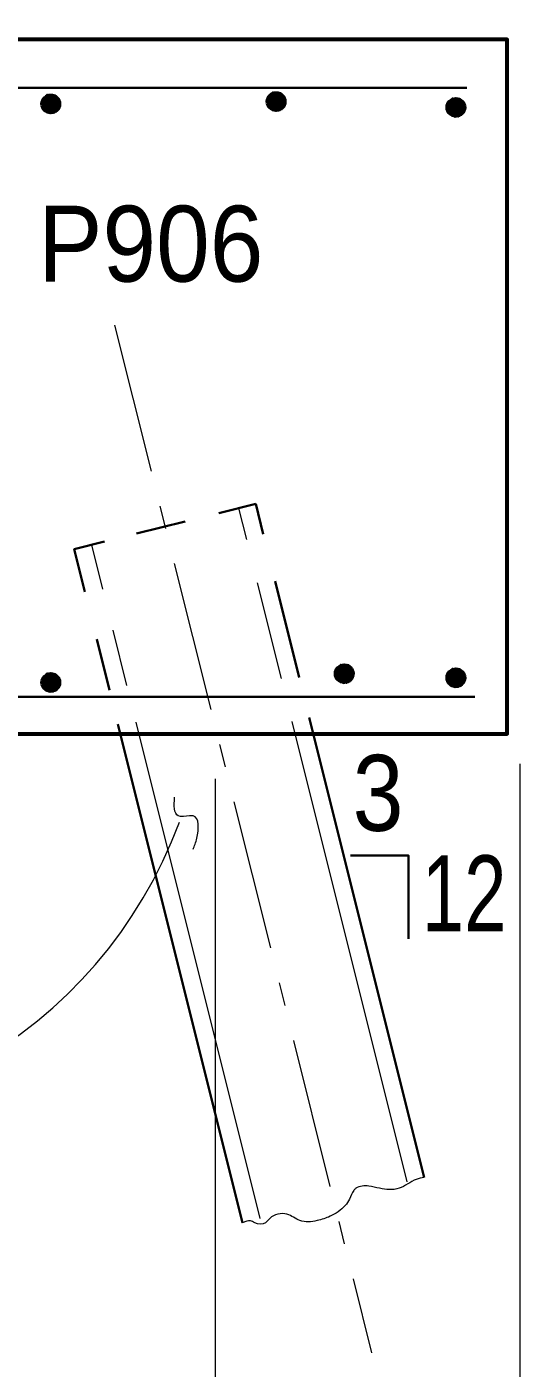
# Model space of a CAD drawing. Extents: x 144 to 252, y 360 to 425.
# Drawn here: x 196.74 to 198.87, y 367 to 372.8 of the extents above; entities that cross this region are included whole.
import ezdxf
from ezdxf.enums import TextEntityAlignment as Align

# ---------------------------------------------------------------- set-up
doc = ezdxf.new("R2010")
doc.units = 0
doc.header["$LTSCALE"] = 0.13
doc.linetypes.add('DOT_DASHED', pattern=[7.7, 5, -1.2, 0.3, -1.2])
for name, color, linetype, lineweight in [('1', 7, 'Continuous', 40), ('14', 7, 'Continuous', 13), ('16', 7, 'Continuous', 13), ('3', 7, 'Continuous', 13), ('4', 7, 'Continuous', 35), ('5', 7, 'Continuous', 35)]:
    doc.layers.add(name, color=color, linetype=linetype, lineweight=lineweight)

msp = doc.modelspace()

# ---------------------------------------------------------------- linework, layer by layer
at = {"layer": '1'}
for p, q in [((197.785, 372.4983), (197.7825, 372.4533)), ((197.7875, 372.4983), (197.785, 372.4533)), ((197.785, 372.4983), (197.845, 372.4883)), ((197.7875, 372.5033), (197.845, 372.4933)), ((197.79, 372.4983), (197.7875, 372.4533)), ((197.7925, 372.4983), (197.79, 372.4533)), ((197.795, 372.4983), (197.7925, 372.4533)), ((197.8, 372.4983), (197.7975, 372.4533)), ((197.8025, 372.4983), (197.8, 372.4533)), ((197.805, 372.4983), (197.8025, 372.4533)), ((197.8075, 372.4983), (197.805, 372.4533)), ((197.81, 372.4983), (197.8075, 372.4533)), ((197.8125, 372.4983), (197.81, 372.4533)), ((197.815, 372.4983), (197.8125, 372.4533)), ((196.8038, 372.4457), (196.8638, 372.4357)), ((196.8063, 372.4607), (196.8663, 372.4482)), ((196.8063, 372.4532), (196.8663, 372.4432)), ((196.8063, 372.4507), (196.8638, 372.4407)), ((196.8063, 372.4482), (196.8638, 372.4382)), ((196.8113, 372.4882), (196.8088, 372.4432)), ((196.8088, 372.4732), (196.8688, 372.4632)), ((196.8088, 372.4707), (196.8688, 372.4582)), ((196.8088, 372.4682), (196.8663, 372.4557)), ((196.8088, 372.4657), (196.8663, 372.4532)), ((196.8138, 372.4882), (196.8113, 372.4432)), ((196.8113, 372.4882), (196.8713, 372.4782)), ((196.8113, 372.4857), (196.8713, 372.4757)), ((196.8113, 372.4832), (196.8713, 372.4707)), ((196.8113, 372.4807), (196.8713, 372.4682)), ((196.8113, 372.4757), (196.8688, 372.4657)), ((196.8138, 372.4932), (196.8713, 372.4832)), ((196.8163, 372.4882), (196.8138, 372.4432)), ((196.8188, 372.4882), (196.8163, 372.4432)), ((196.8213, 372.4882), (196.8188, 372.4432)), ((196.8263, 372.4882), (196.8238, 372.4432)), ((196.8288, 372.4882), (196.8263, 372.4432)), ((196.8313, 372.4882), (196.8288, 372.4432)), ((196.8338, 372.4882), (196.8313, 372.4432)), ((196.8363, 372.4882), (196.8338, 372.4432)), ((196.8388, 372.4882), (196.8363, 372.4432)), ((196.8413, 372.4882), (196.8388, 372.4432)), ((196.8463, 372.4857), (196.8413, 372.4407)), ((196.8513, 372.4857), (196.8463, 372.4407)), ((196.8538, 372.4857), (196.8513, 372.4407)), ((196.8538, 372.4857), (196.8513, 372.4407)), ((196.8563, 372.4857), (196.8538, 372.4407)), ((196.8588, 372.4857), (196.8563, 372.4407)), ((196.8613, 372.4857), (196.8588, 372.4407)), ((196.8638, 372.4857), (196.8613, 372.4407)), ((196.8663, 372.4857), (196.8638, 372.4407)), ((196.8688, 372.4857), (196.8663, 372.4407)), ((196.8738, 372.4857), (196.8713, 372.4407)), ((197.7775, 372.4558), (197.8375, 372.4458)), ((197.78, 372.4708), (197.84, 372.4583)), ((197.78, 372.4633), (197.84, 372.4533)), ((197.78, 372.4608), (197.8375, 372.4508)), ((197.78, 372.4583), (197.8375, 372.4483)), ((197.7825, 372.4833), (197.8425, 372.4733)), ((197.7825, 372.4808), (197.8425, 372.4683)), ((197.7825, 372.4783), (197.84, 372.4658)), ((197.7825, 372.4758), (197.84, 372.4633)), ((197.785, 372.4958), (197.845, 372.4858)), ((197.785, 372.4933), (197.845, 372.4808)), ((197.785, 372.4908), (197.845, 372.4783)), ((197.785, 372.4858), (197.8425, 372.4758)), ((197.82, 372.4958), (197.815, 372.4508)), ((197.825, 372.4958), (197.82, 372.4508)), ((197.8275, 372.4958), (197.825, 372.4508)), ((197.8275, 372.4958), (197.825, 372.4508)), ((197.83, 372.4958), (197.8275, 372.4508)), ((197.8325, 372.4958), (197.83, 372.4508)), ((197.835, 372.4958), (197.8325, 372.4508)), ((197.8375, 372.4958), (197.835, 372.4508)), ((197.84, 372.4958), (197.8375, 372.4508)), ((197.8425, 372.4958), (197.84, 372.4508)), ((197.8475, 372.4958), (197.845, 372.4508)), ((198.5563, 372.4457), (198.6163, 372.4332)), ((198.5613, 372.4733), (198.5588, 372.4282)), ((198.5588, 372.4582), (198.6188, 372.4482)), ((198.5588, 372.4557), (198.6188, 372.4432)), ((198.5588, 372.4532), (198.6163, 372.4407)), ((198.5588, 372.4507), (198.6163, 372.4382)), ((198.5638, 372.4733), (198.5613, 372.4282)), ((198.5613, 372.4733), (198.6213, 372.4632)), ((198.5613, 372.4708), (198.6213, 372.4607)), ((198.5613, 372.4683), (198.6213, 372.4557)), ((198.5613, 372.4658), (198.6213, 372.4532)), ((198.5613, 372.4607), (198.6188, 372.4507)), ((198.5638, 372.4783), (198.6213, 372.4683)), ((198.5663, 372.4733), (198.5638, 372.4282)), ((198.5688, 372.4733), (198.5663, 372.4282)), ((198.5713, 372.4733), (198.5688, 372.4282)), ((198.5763, 372.4733), (198.5738, 372.4282)), ((198.5788, 372.4733), (198.5763, 372.4282)), ((198.5813, 372.4733), (198.5788, 372.4282)), ((198.5838, 372.4733), (198.5813, 372.4282)), ((198.5863, 372.4733), (198.5838, 372.4282)), ((198.5888, 372.4733), (198.5863, 372.4282)), ((198.5913, 372.4733), (198.5888, 372.4282)), ((198.5963, 372.4708), (198.5913, 372.4257)), ((198.6013, 372.4708), (198.5963, 372.4257)), ((198.6038, 372.4708), (198.6013, 372.4257)), ((198.6038, 372.4708), (198.6013, 372.4257)), ((198.6063, 372.4708), (198.6038, 372.4257)), ((198.6088, 372.4708), (198.6063, 372.4257)), ((198.6113, 372.4708), (198.6088, 372.4257)), ((198.6138, 372.4708), (198.6113, 372.4257)), ((198.6163, 372.4708), (198.6138, 372.4257)), ((198.6188, 372.4708), (198.6163, 372.4257)), ((198.6238, 372.4708), (198.6213, 372.4257)), ((198.5538, 372.4307), (198.6138, 372.4207)), ((198.5563, 372.4382), (198.6163, 372.4282)), ((198.5563, 372.4357), (198.6138, 372.4257)), ((198.5563, 372.4332), (198.6138, 372.4232)), ((198.079, 370.0264), (198.0765, 369.9814)), ((198.0765, 370.0114), (198.1365, 370.0014)), ((198.0765, 370.0089), (198.1365, 369.9964)), ((198.0765, 370.0064), (198.134, 369.9939)), ((198.0815, 370.0264), (198.079, 369.9814)), ((198.079, 370.0264), (198.139, 370.0164)), ((198.079, 370.0239), (198.139, 370.0139)), ((198.079, 370.0214), (198.139, 370.0089)), ((198.079, 370.0189), (198.139, 370.0064)), ((198.079, 370.0139), (198.1365, 370.0039)), ((198.0815, 370.0314), (198.139, 370.0214)), ((198.084, 370.0264), (198.0815, 369.9814)), ((198.0865, 370.0264), (198.084, 369.9814)), ((198.089, 370.0264), (198.0865, 369.9814)), ((198.094, 370.0264), (198.0915, 369.9814)), ((198.0965, 370.0264), (198.094, 369.9814)), ((198.099, 370.0264), (198.0965, 369.9814)), ((198.1015, 370.0264), (198.099, 369.9814)), ((198.104, 370.0264), (198.1015, 369.9814)), ((198.1065, 370.0264), (198.104, 369.9814)), ((198.109, 370.0264), (198.1065, 369.9814)), ((198.114, 370.0239), (198.109, 369.9789)), ((198.119, 370.0239), (198.114, 369.9789)), ((198.1215, 370.0239), (198.119, 369.9789)), ((198.1215, 370.0239), (198.119, 369.9789)), ((198.124, 370.0239), (198.1215, 369.9789)), ((198.1265, 370.0239), (198.124, 369.9789)), ((198.129, 370.0239), (198.1265, 369.9789)), ((198.1315, 370.0239), (198.129, 369.9789)), ((198.134, 370.0239), (198.1315, 369.9789)), ((198.1365, 370.0239), (198.134, 369.9789)), ((198.1415, 370.0239), (198.139, 369.9789)), ((198.5613, 370.0087), (198.5588, 369.9637)), ((198.5638, 370.0087), (198.5613, 369.9637)), ((198.5613, 370.0087), (198.6213, 369.9987)), ((198.5613, 370.0062), (198.6213, 369.9962)), ((198.5638, 370.0137), (198.6213, 370.0037)), ((198.5663, 370.0087), (198.5638, 369.9637)), ((198.5688, 370.0087), (198.5663, 369.9637)), ((198.5713, 370.0087), (198.5688, 369.9637)), ((198.5763, 370.0087), (198.5738, 369.9637)), ((198.5788, 370.0087), (198.5763, 369.9637)), ((198.5813, 370.0087), (198.5788, 369.9637)), ((198.5838, 370.0087), (198.5813, 369.9637)), ((198.5863, 370.0087), (198.5838, 369.9637)), ((198.5888, 370.0087), (198.5863, 369.9637)), ((198.5913, 370.0087), (198.5888, 369.9637)), ((198.5963, 370.0062), (198.5913, 369.9612)), ((198.6013, 370.0062), (198.5963, 369.9612)), ((198.6038, 370.0062), (198.6013, 369.9612)), ((198.6038, 370.0062), (198.6013, 369.9612)), ((198.6063, 370.0062), (198.6038, 369.9612)), ((198.6088, 370.0062), (198.6063, 369.9612)), ((198.6113, 370.0062), (198.6088, 369.9612)), ((198.6138, 370.0062), (198.6113, 369.9612)), ((198.6163, 370.0062), (198.6138, 369.9612)), ((198.6188, 370.0062), (198.6163, 369.9612)), ((198.6238, 370.0062), (198.6213, 369.9612)), ((196.8063, 369.9607), (196.8663, 369.9482)), ((196.8063, 369.9532), (196.8663, 369.9432)), ((196.8063, 369.9507), (196.8638, 369.9407)), ((196.8063, 369.9482), (196.8638, 369.9382)), ((196.8113, 369.9882), (196.8088, 369.9432)), ((196.8088, 369.9732), (196.8688, 369.9632)), ((196.8088, 369.9707), (196.8688, 369.9582)), ((196.8088, 369.9682), (196.8663, 369.9557)), ((196.8088, 369.9657), (196.8663, 369.9532)), ((196.8138, 369.9882), (196.8113, 369.9432)), ((196.8113, 369.9882), (196.8713, 369.9782)), ((196.8113, 369.9857), (196.8713, 369.9757)), ((196.8113, 369.9832), (196.8713, 369.9707)), ((196.8113, 369.9807), (196.8713, 369.9682)), ((196.8113, 369.9757), (196.8688, 369.9657)), ((196.8138, 369.9932), (196.8713, 369.9832)), ((196.8163, 369.9882), (196.8138, 369.9432)), ((196.8188, 369.9882), (196.8163, 369.9432)), ((196.8213, 369.9882), (196.8188, 369.9432)), ((196.8263, 369.9882), (196.8238, 369.9432)), ((196.8288, 369.9882), (196.8263, 369.9432)), ((196.8313, 369.9882), (196.8288, 369.9432)), ((196.8338, 369.9882), (196.8313, 369.9432)), ((196.8363, 369.9882), (196.8338, 369.9432)), ((196.8388, 369.9882), (196.8363, 369.9432)), ((196.8413, 369.9882), (196.8388, 369.9432)), ((196.8463, 369.9857), (196.8413, 369.9407)), ((196.8513, 369.9857), (196.8463, 369.9407)), ((196.8538, 369.9857), (196.8513, 369.9407)), ((196.8538, 369.9857), (196.8513, 369.9407)), ((196.8563, 369.9857), (196.8538, 369.9407)), ((196.8588, 369.9857), (196.8563, 369.9407)), ((196.8613, 369.9857), (196.8588, 369.9407)), ((196.8638, 369.9857), (196.8613, 369.9407)), ((196.8663, 369.9857), (196.8638, 369.9407)), ((196.8688, 369.9857), (196.8663, 369.9407)), ((196.8738, 369.9857), (196.8713, 369.9407)), ((198.0715, 369.9839), (198.1315, 369.9739)), ((198.074, 369.9989), (198.134, 369.9864)), ((198.074, 369.9914), (198.134, 369.9814)), ((198.074, 369.9889), (198.1315, 369.9789)), ((198.074, 369.9864), (198.1315, 369.9764)), ((198.0765, 370.0039), (198.134, 369.9914)), ((198.5538, 369.9662), (198.6138, 369.9562)), ((198.5563, 369.9812), (198.6163, 369.9687)), ((198.5563, 369.9737), (198.6163, 369.9637)), ((198.5563, 369.9712), (198.6138, 369.9612)), ((198.5563, 369.9687), (198.6138, 369.9587)), ((198.5588, 369.9937), (198.6188, 369.9837)), ((198.5588, 369.9912), (198.6188, 369.9787)), ((198.5588, 369.9887), (198.6163, 369.9762)), ((198.5588, 369.9862), (198.6163, 369.9737)), ((198.5613, 370.0037), (198.6213, 369.9912)), ((198.5613, 370.0012), (198.6213, 369.9887)), ((198.5613, 369.9962), (198.6188, 369.9862)), ((196.8038, 369.9457), (196.8638, 369.9357))]:
    msp.add_line(p, q, dxfattribs=at)
at = {"layer": '1', "lineweight": 60}
msp.add_lwpolyline([(188.8108, 369.7427), (198.8108, 369.7427), (198.8108, 372.7427), (194.0608, 372.7427), (194.0608, 372.9927), (193.5608, 372.9927), (193.5608, 372.7427), (188.8108, 372.7427)], close=True, dxfattribs=at)
at = {"layer": '1'}
for points in [[(196.7988, 372.4632), (196.8763, 372.4732), (196.8063, 372.4882), (196.8763, 372.4557), (196.8038, 372.4432), (196.8638, 372.4332), (196.8638, 372.4957), (196.8363, 372.4257), (196.8438, 372.5032), (196.8138, 372.4332), (196.8238, 372.5032), (196.8488, 372.4257), (196.8013, 372.4782), (196.8738, 372.4832), (196.8238, 372.4282), (196.8563, 372.5007), (196.8063, 372.4882), (196.8038, 372.4432), (196.8363, 372.4257), (196.8638, 372.4332), (196.8763, 372.4557), (196.8738, 372.4832), (196.8563, 372.5007), (196.8363, 372.4682), (196.8713, 372.4407), (196.8138, 372.4332), (196.8363, 372.4682), (196.8038, 372.4832), (196.8338, 372.5032), (196.8363, 372.4707), (196.8613, 372.4332), (196.8013, 372.4707), (196.8413, 372.4807), (196.8638, 372.4957)], [(197.7725, 372.4733), (197.85, 372.4833), (197.78, 372.4983), (197.85, 372.4658), (197.7775, 372.4533), (197.8375, 372.4433), (197.8375, 372.5058), (197.81, 372.4358), (197.8175, 372.5133), (197.7875, 372.4433), (197.7975, 372.5133), (197.8225, 372.4358), (197.775, 372.4883), (197.8475, 372.4933), (197.7975, 372.4383), (197.83, 372.5108), (197.78, 372.4983), (197.7775, 372.4533), (197.81, 372.4358), (197.8375, 372.4433), (197.85, 372.4658), (197.8475, 372.4933), (197.83, 372.5108), (197.81, 372.4783), (197.845, 372.4508), (197.7875, 372.4433), (197.81, 372.4783), (197.7775, 372.4933), (197.8075, 372.5133), (197.81, 372.4808), (197.835, 372.4433), (197.775, 372.4808), (197.815, 372.4908), (197.8375, 372.5058)], [(198.5488, 372.4482), (198.6263, 372.4582), (198.5563, 372.4733), (198.6263, 372.4407), (198.5538, 372.4282), (198.6138, 372.4183), (198.6138, 372.4808), (198.5863, 372.4108), (198.5938, 372.4882), (198.5638, 372.4183), (198.5738, 372.4882), (198.5988, 372.4108), (198.5513, 372.4632), (198.6238, 372.4683), (198.5738, 372.4133), (198.6063, 372.4857), (198.5563, 372.4733), (198.5538, 372.4282), (198.5863, 372.4108), (198.6138, 372.4183), (198.6263, 372.4407), (198.6238, 372.4683), (198.6063, 372.4857), (198.5863, 372.4532), (198.6213, 372.4257), (198.5638, 372.4183), (198.5863, 372.4532), (198.5538, 372.4683), (198.5838, 372.4882), (198.5863, 372.4557), (198.6113, 372.4183), (198.5513, 372.4557), (198.5913, 372.4658), (198.6138, 372.4808)], [(198.0665, 370.0014), (198.144, 370.0114), (198.074, 370.0264), (198.144, 369.9939), (198.0715, 369.9814), (198.1315, 369.9714), (198.1315, 370.0339), (198.104, 369.9639), (198.1115, 370.0414), (198.0815, 369.9714), (198.0915, 370.0414), (198.1165, 369.9639), (198.069, 370.0164), (198.1415, 370.0214), (198.0915, 369.9664), (198.124, 370.0389), (198.074, 370.0264), (198.0715, 369.9814), (198.104, 369.9639), (198.1315, 369.9714), (198.144, 369.9939), (198.1415, 370.0214), (198.124, 370.0389), (198.104, 370.0064), (198.139, 369.9789), (198.0815, 369.9714), (198.104, 370.0064), (198.0715, 370.0214), (198.1015, 370.0414), (198.104, 370.0089), (198.129, 369.9714), (198.069, 370.0089), (198.109, 370.0189), (198.1315, 370.0339)], [(198.5488, 369.9837), (198.6263, 369.9937), (198.5563, 370.0087), (198.6263, 369.9762), (198.5538, 369.9637), (198.6138, 369.9537), (198.6138, 370.0162), (198.5863, 369.9462), (198.5938, 370.0237), (198.5638, 369.9537), (198.5738, 370.0237), (198.5988, 369.9462), (198.5513, 369.9987), (198.6238, 370.0037), (198.5738, 369.9487), (198.6063, 370.0212), (198.5563, 370.0087), (198.5538, 369.9637), (198.5863, 369.9462), (198.6138, 369.9537), (198.6263, 369.9762), (198.6238, 370.0037), (198.6063, 370.0212), (198.5863, 369.9887), (198.6213, 369.9612), (198.5638, 369.9537), (198.5863, 369.9887), (198.5538, 370.0037), (198.5838, 370.0237), (198.5863, 369.9912), (198.6113, 369.9537), (198.5513, 369.9912), (198.5913, 370.0012), (198.6138, 370.0162)], [(196.7988, 369.9632), (196.8763, 369.9732), (196.8063, 369.9882), (196.8763, 369.9557), (196.8038, 369.9432), (196.8638, 369.9332), (196.8638, 369.9957), (196.8363, 369.9257), (196.8438, 370.0032), (196.8138, 369.9332), (196.8238, 370.0032), (196.8488, 369.9257), (196.8013, 369.9782), (196.8738, 369.9832), (196.8238, 369.9282), (196.8563, 370.0007), (196.8063, 369.9882), (196.8038, 369.9432), (196.8363, 369.9257), (196.8638, 369.9332), (196.8763, 369.9557), (196.8738, 369.9832), (196.8563, 370.0007), (196.8363, 369.9682), (196.8713, 369.9407), (196.8138, 369.9332), (196.8363, 369.9682), (196.8038, 369.9832), (196.8338, 370.0032), (196.8363, 369.9707), (196.8613, 369.9332), (196.8013, 369.9707), (196.8413, 369.9807), (196.8638, 369.9957)]]:
    msp.add_lwpolyline(points, dxfattribs=at)
for centre in [(196.8388, 372.4647), (197.8125, 372.4748), (198.5888, 372.4498), (196.8388, 369.9647), (198.1065, 370.0029), (198.5888, 369.9852)]:
    msp.add_circle(centre, 0.0396, dxfattribs=at)
at = {"layer": '16', "lineweight": 35}
msp.add_lwpolyline([(198.1339, 369.2176), (198.3839, 369.2176), (198.3839, 368.8567)], dxfattribs=at)
at = {"layer": '16'}
msp.add_arc((195.5071, 370.061), 2.0128, 259.05014, 339.66456, dxfattribs=at)
msp.add_spline([(197.4537, 369.2439), (197.4698, 369.2921), (197.4537, 369.3884), (197.4377, 369.3884), (197.3895, 369.3884), (197.3734, 369.4688)], degree=3, dxfattribs=at)
at = {"layer": '3'}
for p, q in [((198.8667, 366.2792), (198.8667, 369.6132)), ((197.5501, 366.215), (197.5501, 369.549))]:
    msp.add_line(p, q, dxfattribs=at)
at = {"layer": '4'}
for p, q in [((189.0608, 372.5343), (198.6356, 372.5343)), ((189.0608, 369.9021), (198.6711, 369.9021))]:
    msp.add_line(p, q, dxfattribs=at)
at = {"layer": '5', "linetype": 'DOT_DASHED', "lineweight": 13}
msp.add_line((197.1147, 371.5091), (198.2248, 367.0677), dxfattribs=at)
at = {"layer": '5'}
for p, q in [((197.7243, 370.7367), (197.5649, 370.6968)), ((197.7243, 370.7367), (197.7569, 370.6063)), ((197.4187, 370.6603), (197.2091, 370.6079)), ((197.8077, 370.403), (197.9118, 369.9865)), ((197.0372, 370.1525), (197.0925, 369.9311)), ((197.129, 369.785), (197.6677, 367.6302)), ((197.955, 369.814), (198.4518, 367.8262))]:
    msp.add_line(p, q, dxfattribs=at)
at = {"layer": '5', "lineweight": 13}
for p, q in [((197.65, 370.7181), (197.6838, 370.5832)), ((197.0145, 370.5592), (197.0623, 370.3681)), ((197.7307, 370.3953), (197.8342, 369.9814)), ((197.1065, 370.1911), (197.1662, 369.9523)), ((197.2058, 369.7936), (197.742, 367.6488)), ((197.8804, 369.7963), (198.3775, 367.8076))]:
    msp.add_line(p, q, dxfattribs=at)
at = {"layer": '5'}
msp.add_lwpolyline([(197.0712, 370.5734), (196.9402, 370.5407), (196.9862, 370.3567)], dxfattribs=at)
at = {"layer": '5', "lineweight": 13}
msp.add_spline([(198.4518, 367.8262), (198.4179, 367.8177), (198.3433, 367.7791), (198.2595, 367.7791), (198.213, 367.7884), (198.1572, 367.7791), (198.1478, 367.7698), (198.1292, 367.7326), (198.1106, 367.7047), (198.0455, 367.6581), (197.9896, 367.6395), (197.9152, 367.6395), (197.8593, 367.6674), (197.7848, 367.6488), (197.7662, 367.6302), (197.7197, 367.6302), (197.7016, 367.6387), (197.6677, 367.6302)], degree=3, dxfattribs=at)

# ---------------------------------------------------------------- texts
at = {"layer": '14', "width": 0.95}
msp.add_text('P906', height=0.3281, dxfattribs=at).set_placement((197.2707, 371.6968), align=Align.CENTER)
at = {"layer": '16', "width": 0.9}
msp.add_text('3', height=0.3281, dxfattribs=at).set_placement((198.2528, 369.3237), align=Align.CENTER)
at = {"layer": '16', "width": 0.75}
msp.add_text('12', height=0.3281, dxfattribs=at).set_placement((198.8077, 368.8897), align=Align.RIGHT)

doc.saveas('drawing.dxf')
